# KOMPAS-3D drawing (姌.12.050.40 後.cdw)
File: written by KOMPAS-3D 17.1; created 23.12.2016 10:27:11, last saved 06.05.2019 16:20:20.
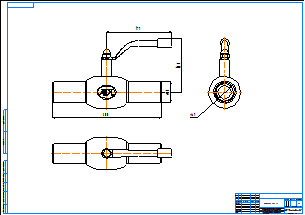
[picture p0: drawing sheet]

Sheet 1: A1, landscape

Title block, sheet 1: name: КШ.12.050.40 сс; material: Внимание! Данный продукт является объектом авторского права ООО «Торговый Дом АДЛ». / Запрещается изменение, копирование, распространение / (в том числе путем копирования на другие сайты и ресурсы в Интернете) / или любое иное использование информации и объектов без предварительного / согласия правообладателя (ООО «Торговый Дом АДЛ»).; sheets: 1; organisation: ООО "Торговый дом АДЛ"; sheet format: A1; stored path: C:\Users\tra\Desktop\2д чертежи\Шаровые краны БИВАЛ\КШ_Бивал_серия_11_12\KOMPAS_2D\КШ.12.050.40 сс.cdw

Views: Вид 1, Проекционный вид 2, Проекционный вид 3
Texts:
  Klimkovich
  ADL
Dimensions and other numbers on the sheet: 300; 57; 179; 148; 49; 1:1; 1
